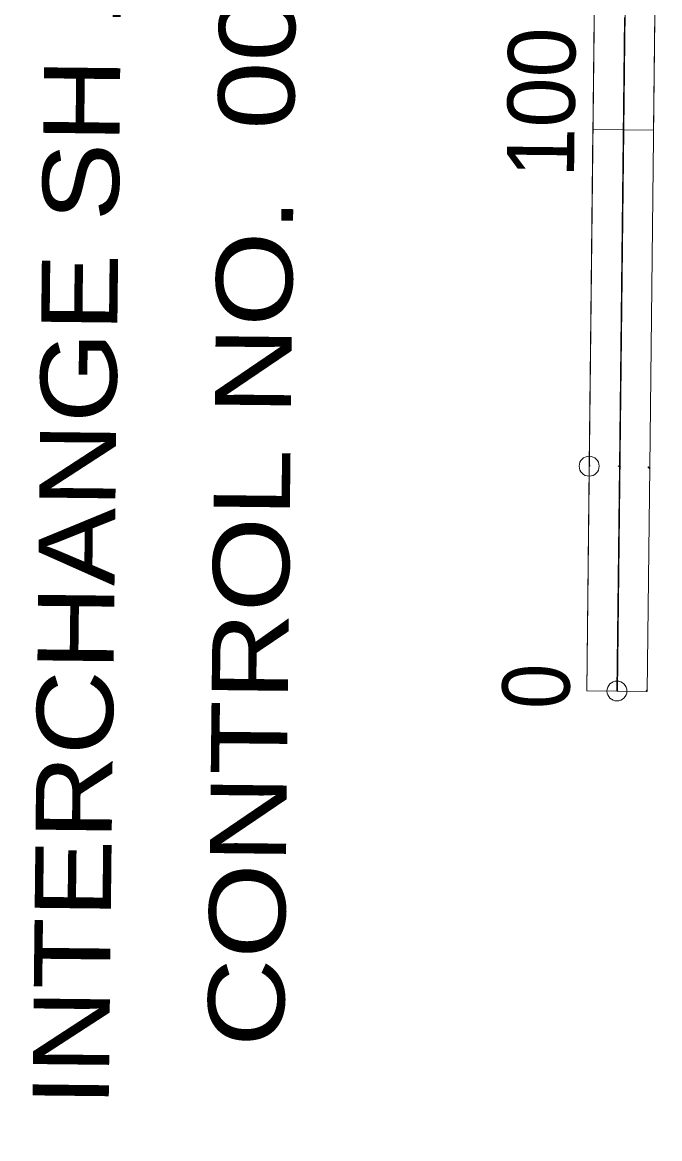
# Model space of a CAD drawing. Extents: x 2356576 to 2377878, y 6966390 to 6990634.
# Drawn here: x 2366724.3 to 2366837.9, y 6990063.3 to 6990262.2 of the extents above; entities that cross this region are included whole.
import ezdxf

# ---------------------------------------------------------------- set-up
doc = ezdxf.new("R2010")
doc.units = 0
doc.header["$LTSCALE"] = 7.1
doc.header["$PDMODE"] = 32
doc.header["$PDSIZE"] = 3.55
doc.layers.add('19', color=7, linetype='Continuous', lineweight=13)
doc.layers.add('8', color=7, linetype='Continuous', lineweight=13)

msp = doc.modelspace()

# ---------------------------------------------------------------- linework, layer by layer
at = {"layer": '19'}
for p, q in [((2366824.855, 6990143.089), (2366827.075, 6990343.078)), ((2366825.299, 6990183.087), (2366826.187, 6990263.082)), ((2366831.58, 6990263.022), (2366830.692, 6990183.027)), ((2366836.085, 6990182.967), (2366836.974, 6990262.962)), ((2366825.965, 6990243.083), (2366836.752, 6990242.963)), ((2366824.855, 6990143.089), (2366825.299, 6990183.087)), ((2366825.389, 6990183.086), (2366825.3, 6990183.177)), ((2366825.483, 6990183.085), (2366825.301, 6990183.271)), ((2366830.478, 6990183.029), (2366830.695, 6990183.241)), ((2366830.572, 6990183.028), (2366830.693, 6990183.146)), ((2366830.248, 6990143.029), (2366830.692, 6990183.027)), ((2366830.667, 6990183.027), (2366830.692, 6990183.052)), ((2366830.691, 6990182.951), (2366830.767, 6990183.026)), ((2366830.691, 6990182.857), (2366830.861, 6990183.025)), ((2366836.082, 6990182.627), (2366835.746, 6990182.971)), ((2366836.083, 6990182.722), (2366835.841, 6990182.97)), ((2366830.248, 6990143.029), (2366824.855, 6990143.089)), ((2366830.33, 6990143.028), (2366830.249, 6990143.111)), ((2366830.425, 6990143.027), (2366830.25, 6990143.205)), ((2366835.389, 6990142.972), (2366835.644, 6990143.221)), ((2366835.483, 6990142.971), (2366835.643, 6990143.127))]:
    msp.add_line(p, q, dxfattribs=at)
for points in [[(2366831.474, 6990243.042), (2366832.584, 6990343.017), (2366837.863, 6990342.958), (2366836.752, 6990242.983)], [(2366824.855, 6990143.089), (2366825.965, 6990243.103), (2366831.474, 6990243.042), (2366830.363, 6990143.027)]]:
    msp.add_lwpolyline(points, close=True, dxfattribs=at)
msp.add_lwpolyline([(2366836.085, 6990182.967), (2366835.641, 6990142.969), (2366830.248, 6990143.029)], dxfattribs=at)
for p in [(2366825.299, 6990183.087), (2366830.248, 6990143.029)]:
    msp.add_point(p, dxfattribs=at)
at = {"layer": '8'}
for p, q in [((2366824.855, 6990143.089), (2366827.075, 6990343.078)), ((2366825.299, 6990183.087), (2366826.187, 6990263.082)), ((2366831.58, 6990263.022), (2366830.692, 6990183.027)), ((2366836.085, 6990182.967), (2366836.974, 6990262.962)), ((2366825.965, 6990243.083), (2366836.752, 6990242.963)), ((2366824.855, 6990143.089), (2366825.299, 6990183.087)), ((2366825.389, 6990183.086), (2366825.3, 6990183.177)), ((2366825.483, 6990183.085), (2366825.301, 6990183.271)), ((2366830.478, 6990183.029), (2366830.695, 6990183.241)), ((2366830.572, 6990183.028), (2366830.693, 6990183.146)), ((2366830.248, 6990143.029), (2366830.692, 6990183.027)), ((2366830.667, 6990183.027), (2366830.692, 6990183.052)), ((2366830.691, 6990182.951), (2366830.767, 6990183.026)), ((2366830.691, 6990182.857), (2366830.861, 6990183.025)), ((2366836.082, 6990182.627), (2366835.746, 6990182.971)), ((2366836.083, 6990182.722), (2366835.841, 6990182.97)), ((2366830.248, 6990143.029), (2366824.855, 6990143.089)), ((2366830.33, 6990143.028), (2366830.249, 6990143.111)), ((2366830.425, 6990143.027), (2366830.25, 6990143.205)), ((2366835.389, 6990142.972), (2366835.644, 6990143.221)), ((2366835.483, 6990142.971), (2366835.643, 6990143.127))]:
    msp.add_line(p, q, dxfattribs=at)
for points in [[(2366831.474, 6990243.042), (2366832.584, 6990343.017), (2366837.863, 6990342.958), (2366836.752, 6990242.983)], [(2366824.855, 6990143.089), (2366825.965, 6990243.103), (2366831.474, 6990243.042), (2366830.363, 6990143.027)]]:
    msp.add_lwpolyline(points, close=True, dxfattribs=at)
msp.add_lwpolyline([(2366836.085, 6990182.967), (2366835.641, 6990142.969), (2366830.248, 6990143.029)], dxfattribs=at)
for p in [(2366825.299, 6990183.087), (2366830.248, 6990143.029)]:
    msp.add_point(p, dxfattribs=at)

# ---------------------------------------------------------------- texts
at = {"layer": '19'}
for s, height, width, p in [('LIMITS:  NORTH INTERCHANGE SH 121 TO RANDOL MILL ROAD', 13.58, 1.15, (2366737.852, 6989904.165)), ('CONTROL NO.  0008-13-123', 13.58, 1.2, (2366770.906, 6990079.545)), ('0', 12, 0.9, (2366821.777, 6990139.786))]:
    msp.add_text(s, height=height, rotation=89.364, dxfattribs=dict(at, width=width)).set_placement(p)
msp.add_text('100', height=12, rotation=89.364, dxfattribs=at).set_placement((2366822.597, 6990234.438))
at = {"layer": '8'}
for s, height, width, p in [('LIMITS:  NORTH INTERCHANGE SH 121 TO RANDOL MILL ROAD', 13.58, 1.15, (2366737.852, 6989904.165)), ('CONTROL NO.  0008-13-123', 13.58, 1.2, (2366770.906, 6990079.545)), ('0', 12, 0.9, (2366821.777, 6990139.786))]:
    msp.add_text(s, height=height, rotation=89.364, dxfattribs=dict(at, width=width)).set_placement(p)
msp.add_text('100', height=12, rotation=89.364, dxfattribs=at).set_placement((2366822.597, 6990234.438))

doc.saveas('drawing.dxf')
